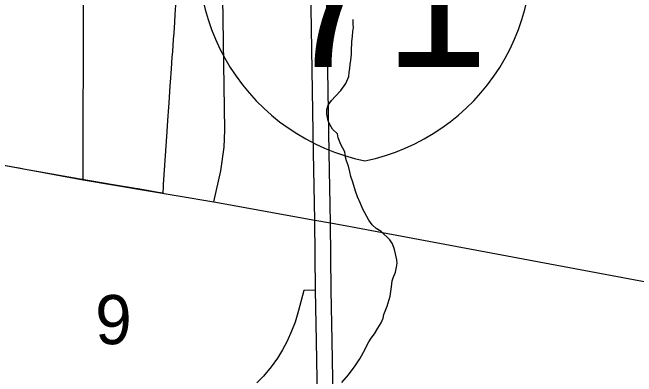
# Model space of a CAD drawing. Extents: x 0 to 34, y -3.9 to 26.2.
# Drawn here: x 7.473 to 8.005, y 19.308 to 19.618 of the extents above; entities that cross this region are included whole.
import ezdxf

# ---------------------------------------------------------------- set-up
doc = ezdxf.new("R2010")
doc.units = 0
for name, color, linetype in [('GM_X_City_Street', 7, 'Continuous'), ('GM_X_County_Road', 7, 'Continuous'), ('GM_X_Interchange_Ramps', 7, 'Continuous'), ('GM_X_Interstate_Location', 7, 'Continuous'), ('GM_X_Interstate_Route', 7, 'Continuous'), ('GM_X_Interstate_Shield', 7, 'Continuous'), ('GM_X_Minor_River', 7, 'Continuous'), ('GM_X_Section_Text', 7, 'Continuous')]:
    doc.layers.add(name, color=color, linetype=linetype)

msp = doc.modelspace()

# ---------------------------------------------------------------- linework, layer by layer
at = {"layer": 'GM_X_City_Street'}
msp.add_line((7.53287, 19.47515), (7.53339, 19.72142), dxfattribs=at)
msp.add_lwpolyline([(7.64417, 19.45634), (7.65027, 19.4828), (7.653, 19.50289), (7.65369, 19.51732), (7.65099, 19.68727), (7.64817, 19.8162), (7.64816, 19.81694), (7.64986, 19.86023)], dxfattribs=at)
at = {"layer": 'GM_X_County_Road'}
for points in [[(6.91045, 19.95426), (6.90346, 19.90083), (6.89591, 19.84303), (6.8943, 19.83077), (6.89497, 19.82657), (6.89638, 19.82401), (6.90047, 19.81658), (6.9452, 19.7465), (6.96045, 19.7226), (6.96455, 19.71872), (7.02086, 19.69221), (7.05976, 19.6739), (7.08787, 19.66066), (7.10286, 19.6536), (7.17357, 19.6231), (7.19002, 19.616), (7.23913, 19.5933), (7.29852, 19.5645), (7.37544, 19.52375), (7.39552, 19.51386), (7.4346, 19.49827), (7.46484, 19.4876), (7.47284, 19.48614)], [(7.47284, 19.48614), (7.53287, 19.47515), (7.61381, 19.46147)], [(7.61381, 19.46147), (7.64417, 19.45634), (7.7304, 19.44074), (7.74375, 19.43838), (7.76077, 19.4352)], [(7.76077, 19.4352), (8.1127, 19.36932), (8.12248, 19.36621), (8.13893, 19.35465), (8.21758, 19.28294), (8.23057, 19.27663), (8.24823, 19.27314), (8.32399, 19.26542), (8.37173, 19.26055)]]:
    msp.add_lwpolyline(points, dxfattribs=at)
at = {"layer": 'GM_X_Interchange_Ramps'}
for points in [[(7.61165, 19.62376), (7.61109, 19.61581), (7.61064, 19.60933), (7.61, 19.60012), (7.60963, 19.59478), (7.6089, 19.58442), (7.60855, 19.57952), (7.60785, 19.56955), (7.60707, 19.5582), (7.60685, 19.55514), (7.60584, 19.54052), (7.60559, 19.53694), (7.60483, 19.52569), (7.60418, 19.51619), (7.60114, 19.47117), (7.60102, 19.46949), (7.60063, 19.46368), (7.59688, 19.46433), (7.57933, 19.46739), (7.57731, 19.46774), (7.57564, 19.46802), (7.5584, 19.47088), (7.55026, 19.47223), (7.53859, 19.47429), (7.53038, 19.47574), (7.48209, 19.48428), (7.47832, 19.48494), (7.47455, 19.48561), (7.45412, 19.48922)], [(7.73096, 19.38119), (7.72096, 19.38066), (7.71649, 19.36383), (7.71346, 19.35375), (7.71053, 19.34602), (7.70676, 19.3377), (7.70284, 19.33038), (7.69845, 19.32327), (7.69314, 19.31581), (7.68662, 19.30793), (7.681, 19.30202)]]:
    msp.add_lwpolyline(points, dxfattribs=at)
at = {"layer": 'GM_X_Interstate_Route'}
for points in [[(7.7314, 19.25551), (7.73271, 19.28929), (7.73184, 19.33776), (7.73096, 19.38119), (7.7304, 19.44074), (7.7292, 19.49831), (7.72657, 19.65667), (7.72591, 19.72707), (7.72657, 19.78168), (7.72833, 19.83059), (7.7314, 19.88674), (7.7382, 19.96438), (7.75465, 20.12713), (7.76364, 20.21574), (7.77568, 20.33229), (7.78338, 20.41423), (7.80443, 20.61842), (7.81145, 20.6908), (7.81338, 20.71176), (7.82882, 20.8641), (7.8333, 20.9)], [(7.74207, 19.22325), (7.74295, 19.23033), (7.7447, 19.25555), (7.74602, 19.28933), (7.74514, 19.3378), (7.74427, 19.38122), (7.74375, 19.43838), (7.74251, 19.49835), (7.73988, 19.6567), (7.73922, 19.72711), (7.73988, 19.78172), (7.74163, 19.83063), (7.7447, 19.88678), (7.7515, 19.96442), (7.76795, 20.12716), (7.77695, 20.21577), (7.78879, 20.33026), (7.79669, 20.41426), (7.81774, 20.61846), (7.82476, 20.6893), (7.82737, 20.70886), (7.84185, 20.85971), (7.84685, 20.9)]]:
    msp.add_lwpolyline(points, dxfattribs=at)
at = {"layer": 'GM_X_Interstate_Shield'}
for centre, start, end in [((7.80858, 19.66527), 165.8066, 258.463), ((7.73755, 19.66527), 281.537, 14.1934)]:
    msp.add_arc(centre, 0.17756, start, end, dxfattribs=at)
at = {"layer": 'GM_X_Minor_River'}
msp.add_lwpolyline([(7.7534, 19.30235), (7.75902, 19.30898), (7.7647, 19.31674), (7.76876, 19.32266), (7.77331, 19.33085), (7.77499, 19.33459), (7.77625, 19.3372), (7.77828, 19.34016), (7.78111, 19.34385), (7.78399, 19.34868), (7.78685, 19.35313), (7.78854, 19.35725), (7.78905, 19.36027), (7.79202, 19.36738), (7.79291, 19.37039), (7.79467, 19.37602), (7.79577, 19.38397), (7.79635, 19.38889), (7.79723, 19.39152), (7.79896, 19.39639), (7.79989, 19.40054), (7.80042, 19.40394), (7.80016, 19.407), (7.79922, 19.41198), (7.79823, 19.41582), (7.79651, 19.42046), (7.79436, 19.42396), (7.78701, 19.4311), (7.78252, 19.43357), (7.77922, 19.43674), (7.77632, 19.44066), (7.77135, 19.44999), (7.76926, 19.45501), (7.76682, 19.46044), (7.76511, 19.46545), (7.76275, 19.47315), (7.76103, 19.47778), (7.76006, 19.48201), (7.7591, 19.48661), (7.75738, 19.49124), (7.75636, 19.49433), (7.75579, 19.49891), (7.75261, 19.50513), (7.75017, 19.51093), (7.74955, 19.51438), (7.7455, 19.51834), (7.74299, 19.52225), (7.74159, 19.52535), (7.74068, 19.53109), (7.74045, 19.5349), (7.74176, 19.53865), (7.7446, 19.54272), (7.74781, 19.5464), (7.7526, 19.55115), (7.75666, 19.55708), (7.75921, 19.56306), (7.75973, 19.56646), (7.76027, 19.57025), (7.76039, 19.57328), (7.76093, 19.57707), (7.76152, 19.58199), (7.76164, 19.58503), (7.76196, 19.59262), (7.76254, 19.59754), (7.7627, 19.60134), (7.76322, 19.60474), (7.76297, 19.60779), (7.76312, 19.61159)], dxfattribs=at)

# ---------------------------------------------------------------- texts
at = {"layer": 'GM_X_Interstate_Location'}
msp.add_text('71', height=0.000189, rotation=0, dxfattribs=at).set_placement((7.73435, 19.59405))
at = {"layer": 'GM_X_Interstate_Shield'}
msp.add_text('71', height=0.118371, dxfattribs=at).set_placement((7.70184, 19.57121))
at = {"layer": 'GM_X_Section_Text'}
msp.add_text('9', height=0.04186, rotation=0, dxfattribs=at).set_placement((7.5431, 19.33507))

doc.saveas('drawing.dxf')
